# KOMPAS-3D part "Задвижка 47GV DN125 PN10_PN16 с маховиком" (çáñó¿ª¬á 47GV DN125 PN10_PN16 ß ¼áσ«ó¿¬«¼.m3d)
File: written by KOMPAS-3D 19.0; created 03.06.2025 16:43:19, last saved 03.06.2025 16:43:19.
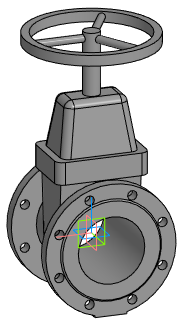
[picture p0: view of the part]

Document properties: Автор: Евгений; Полное имя файла: E:\Dendor Работа Сачек\3D для проекитирвщиков\2.1 Тип 47GV, 47GV.Z Задвижка клиновая фланцевая с обрезиненным клином\stp_Тип 47GV. Задвижка DN40-DN350 с маховиком\Задвижка 47GV DN125 PN10_PN16 с маховиком.m3d

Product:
- Part/product: Задвижка 47GV DN125 PN10_PN16 с маховиком

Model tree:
1. Операция без истории:1  (labels: Задвижка 47GV DN125 PN10_PN16 с маховиком)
